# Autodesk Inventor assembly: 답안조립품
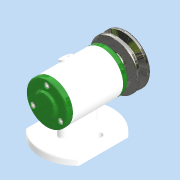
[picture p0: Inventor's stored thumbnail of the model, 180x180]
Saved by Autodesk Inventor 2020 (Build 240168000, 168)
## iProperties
Created: 2022-02
Part Number: 답안조립품
Document SubType Name: Assembly
Designer: 605-4
Author: 605-4
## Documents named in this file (13)
- C:\Users\605-4\Desktop\720206V1025\답안조립품.iam
- C:\Users\605-4\Desktop\720206V1025\본체.ipt
- C:\Users\605-4\Desktop\720206V1025\베어링 6002.ipt
- C:\Users\605-4\Desktop\720206V1025\축.ipt
- C:\Users\605-4\Desktop\720206V1025\뒤커버.ipt
- C:\Users\605-4\Desktop\720206V1025\앞커버.ipt
- C:\Users\605-4\Desktop\720206V1025\오일 실 15 x 25 x 7.ipt
- C:\Users\605-4\Desktop\720206V1025\볼트 M4 x 10.ipt
- C:\Users\605-4\Desktop\720206V1025\키 3 x 3 x 12.ipt
- C:\Users\605-4\Desktop\720206V1025\V벨트풀리.ipt
- C:\Users\605-4\Desktop\720206V1025\평와셔 8 x 17.ipt
- C:\Users\605-4\Desktop\720206V1025\스프링와셔 8.ipt
- C:\Users\605-4\Desktop\720206V1025\너트 M8.ipt
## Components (1 placed, 1 different names)
1. V벨트풀리:1
